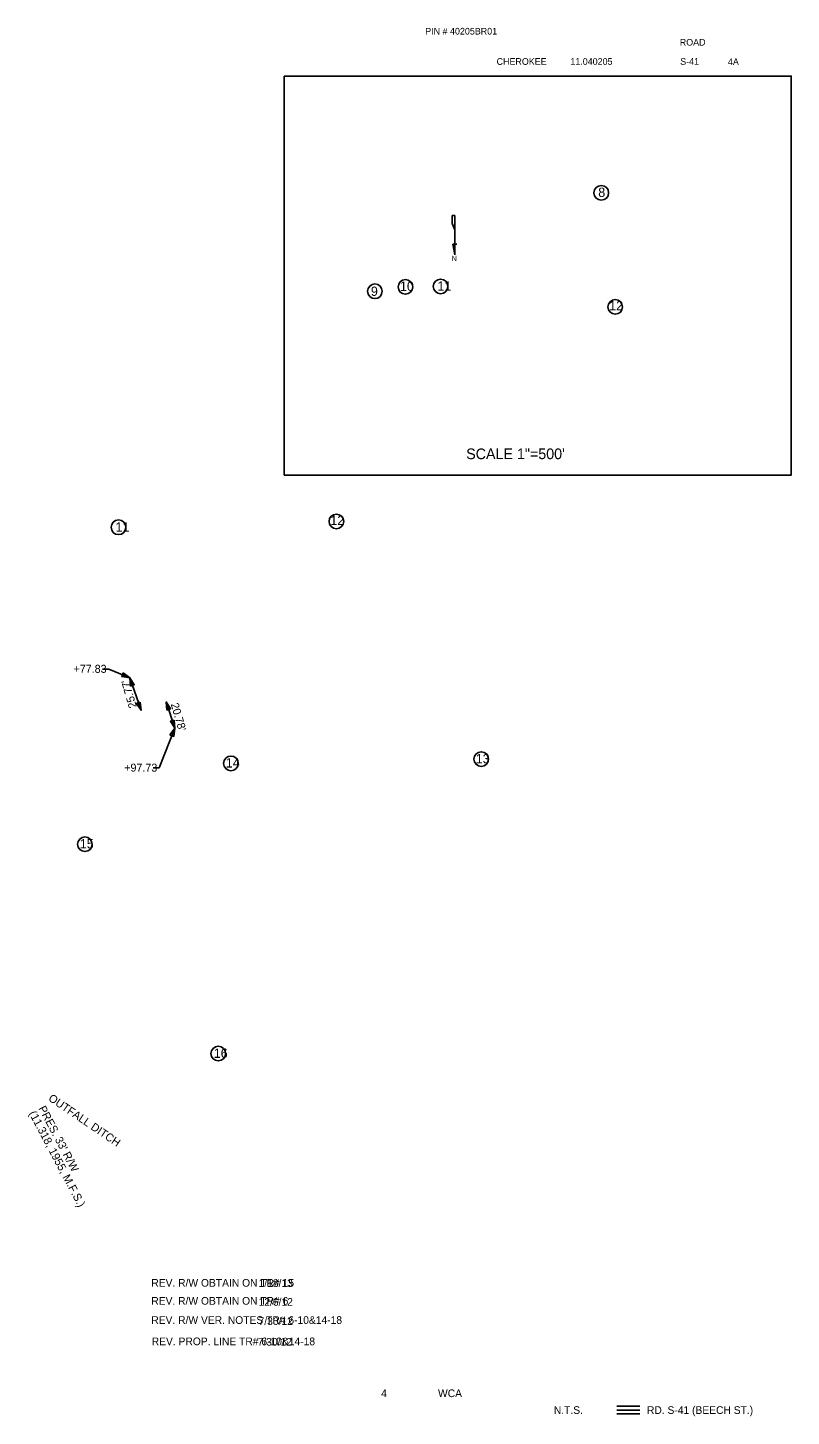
# Model space of a CAD drawing. Extents: x 16384283 to 16385930, y 46199013 to 46200055.
# Drawn here: x 16385358 to 16385930, y 46199013 to 46200055 of the extents above; entities that cross this region are included whole.
import ezdxf

# ---------------------------------------------------------------- set-up
doc = ezdxf.new("R2010")
doc.units = 0
for name, color, linetype in [('Default', 7, 'Continuous'), ('RD_EX_DV_Prop', 7, 'Continuous'), ('RD_EX_H2O', 7, 'Continuous'), ('RD_EX_Misc', 7, 'Continuous'), ('RD_EX_RW_TX', 7, 'Continuous'), ('RD_SHT_Bndy', 7, 'Continuous'), ('RD_SHT_TX', 7, 'Continuous'), ('RD_TX_Drainage', 7, 'Continuous'), ('RD_TX_RoadID', 7, 'Continuous')]:
    doc.layers.add(name, color=color, linetype=linetype)

msp = doc.modelspace()

# ---------------------------------------------------------------- linework, layer by layer
at = {"layer": 'Default'}
for p, q in [((16385799.1, 46199021), (16385816.3, 46199021)), ((16385799.1, 46199018.1), (16385816.3, 46199018.1)), ((16385799.1, 46199015.2), (16385816.3, 46199015.2))]:
    msp.add_line(p, q, dxfattribs=at)
at = {"layer": 'RD_EX_DV_Prop'}
for centre in [(16385787.5, 46199930.8), (16385640.7, 46199860.3), (16385667, 46199860.6), (16385617.8, 46199857), (16385797.9, 46199845.3), (16385588.9, 46199684.4), (16385425.6, 46199680), (16385697.5, 46199506.2), (16385509.9, 46199503), (16385400.4, 46199442.4), (16385500.4, 46199285.4)]:
    msp.add_circle(centre, 5.49, dxfattribs=at)
at = {"layer": 'RD_EX_H2O'}
for p, q in [((16385677.8, 46199913.8), (16385675.8, 46199913.8)), ((16385675.8, 46199913.8), (16385675.8, 46199907.8)), ((16385675.8, 46199907.9), (16385677.8, 46199903.1)), ((16385675.8, 46199907.8), (16385675.8, 46199907.9)), ((16385677.8, 46199903.1), (16385677.8, 46199913.8)), ((16385677.8, 46199903.1), (16385677.8, 46199892.2)), ((16385676.2, 46199892.2), (16385676.2, 46199892.1)), ((16385676.2, 46199892.2), (16385677.8, 46199884.4)), ((16385677.8, 46199892.2), (16385676.2, 46199892.2)), ((16385679.3, 46199892.2), (16385677.8, 46199892.2)), ((16385677.8, 46199884.4), (16385677.8, 46199892.2)), ((16385677.8, 46199884.4), (16385677.8, 46199884.4))]:
    msp.add_line(p, q, dxfattribs=at)
at = {"layer": 'RD_EX_RW_TX'}
for p, q in [((16385413.6, 46199573.7), (16385418.3, 46199573.7)), ((16385434.1, 46199567.2), (16385418.3, 46199573.7)), ((16385434.1, 46199567.2), (16385442.5, 46199542.8)), ((16385467.8, 46199529.4), (16385461.4, 46199549.1)), ((16385467.8, 46199529.4), (16385456.2, 46199499.6)), ((16385451.6, 46199499.6), (16385456.2, 46199499.6))]:
    msp.add_line(p, q, dxfattribs=at)
at = {"layer": 'RD_SHT_Bndy'}
msp.add_lwpolyline([(16385549.8, 46200018.4), (16385929.8, 46200018.4), (16385929.8, 46199719.2), (16385549.8, 46199719.2)], close=True, dxfattribs=at)
at = {"layer": 'RD_TX_Drainage'}
for points in [[(16385429.1, 46199570.8), (16385434.1, 46199567.2), (16385428, 46199568.1)], [(16385434.6, 46199561), (16385434.1, 46199567.2), (16385437.4, 46199562)], [(16385441.9, 46199549), (16385442.5, 46199542.8), (16385439.1, 46199548)], [(16385461.8, 46199542.9), (16385461.4, 46199549.1), (16385464.6, 46199543.9)], [(16385467.3, 46199535.5), (16385467.8, 46199529.4), (16385464.5, 46199534.6)], [(16385464.2, 46199524.3), (16385467.8, 46199529.4), (16385467, 46199523.2)]]:
    msp.add_lwpolyline(points, close=True, dxfattribs=at)

# ---------------------------------------------------------------- texts
at = {"layer": 'RD_EX_DV_Prop'}
for s, p in [('8', (16385785.2, 46199927.7)), ('9', (16385614.8, 46199853.5)), ('10', (16385636.6, 46199857.3)), ('11', (16385664.7, 46199857.4)), ('12', (16385793.4, 46199842.7)), ('12', (16385584.4, 46199681.7)), ('11', (16385423.4, 46199676.8)), ('14', (16385506, 46199499.9)), ('13', (16385693.4, 46199503)), ('15', (16385396.6, 46199439.2)), ('16', (16385497, 46199282.2))]:
    msp.add_text(s, height=7, dxfattribs=at).set_placement(p)
at = {"layer": 'RD_EX_H2O'}
msp.add_text('N', height=4, rotation=180, dxfattribs=at).set_placement((16385679.3, 46199883.6))
at = {"layer": 'RD_EX_Misc'}
for s, p in [('PIN # 40205BR01', (16385655.5, 46200049.5)), ('ROAD', (16385846.3, 46200041.2)), ('CHEROKEE', (16385709, 46200026.8)), ('11.040205 ', (16385764.3, 46200026.8)), ('S-41', (16385846.6, 46200026.8)), ('4A', (16385882.4, 46200026.6))]:
    msp.add_text(s, height=5, dxfattribs=at).set_placement(p)
at = {"layer": 'RD_EX_RW_TX'}
for s, p in [('+77.83', (16385391.9, 46199570.9)), ('+97.73', (16385429.9, 46199496.8))]:
    msp.add_text(s, height=6, dxfattribs=at).set_placement(p)
for s, rotation, p in [("25.77'", 106.3009, (16385439.4, 46199545.4)), ("20.78'", 286.3009, (16385464.7, 46199547.4)), ('(11.318, 1955, M.F.S.)', 297.8262, (16385358.3, 46199240.6)), ("PRES. 33' R/W ", 297.8262, (16385365.4, 46199244.3))]:
    msp.add_text(s, height=6, rotation=rotation, dxfattribs=at).set_placement(p)
at = {"layer": 'RD_SHT_TX'}
for s, height, p in [('SCALE 1"=500\'', 8, (16385686.2, 46199731.1)), ('REV. R/W OBTAIN ON TR# 15', 5.76, (16385450.2, 46199110.6)), ('1/18/13', 5.76, (16385530.6, 46199110.4)), ('REV. R/W OBTAIN ON TR# 6', 5.76, (16385450.2, 46199097.1)), ('12/6/12', 5.76, (16385530.6, 46199096.3)), ('REV. R/W VER. NOTES TR# 6-10&14-18', 5.76, (16385450.2, 46199082.7)), ('7/30/12', 5.76, (16385530.6, 46199081.9)), ('REV. PROP. LINE TR# 6-10&14-18', 5.76, (16385450.5, 46199066.7)), ('7/30/12', 5.76, (16385529.9, 46199066.4)), ('4', 5.76, (16385622.5, 46199027.8)), ('WCA', 5.76, (16385665.1, 46199027.8)), ('RD. S-41 (BEECH ST.)', 5.76, (16385821.7, 46199015.2)), ('N.T.S.', 5.76, (16385751.9, 46199015.2))]:
    msp.add_text(s, height=height, dxfattribs=at).set_placement(p)
at = {"layer": 'RD_TX_RoadID'}
msp.add_text('OUTFALL DITCH', height=6, rotation=325.768, dxfattribs=at).set_placement((16385372.5, 46199250.6))

doc.saveas('drawing.dxf')
